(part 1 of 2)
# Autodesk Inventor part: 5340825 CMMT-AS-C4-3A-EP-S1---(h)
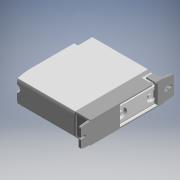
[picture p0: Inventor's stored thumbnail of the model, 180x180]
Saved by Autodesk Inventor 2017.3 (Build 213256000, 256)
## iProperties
Part Number: 5340825 CMMT-AS-C4-3A-EP-S1---(h)
Material: Generic
Catalog Web Link: www.cadenas.de
Description: CMMT-h-housing
Vendor: FESTO
Document SubType Name: Modeling
Designer: partserver
Manufacturer: FESTO
Mass: 1385.12 g
Surface Area: 1266.44 cm^2
Volume: 1385.12 cm^3
Density: 1 g/cm^3
Appearance: PSOLRGB-255-255-255
Category: PARTsolutions
Company: FESTO
Title: 5340825 CMMT-AS-C4-3A-EP-S1---(h)
Author: Cadenas PARTsolutions
Comments: housing
PSOL_IDENT_0: {$CADENAS_DATA\23d-libs\festo\parts\c\cmmt\parts\cmmt_housing.prj},207 {VTYP=3D},{NB=5340825 CMMT-AS
PSOL_IDENT_1: -C4-3A-EP-S1---(h)},{LINA=5340825 CMMT-AS-C4-3A-EP-S1---(h)},{NN=CMMT-h},{DATE=07.10.2020 12:11:43},
PSOL_IDENT_2: {GEOMDATE=07.10.2020 12:11:39},{VERSION=},{LINEID=130},{WBVAR=},{WBNUMERIC=}  {NB=5340825 CMMT-AS-C4
PSOL_IDENT_3: -3A-EP-S1---(h)},{LINA=5340825 CMMT-AS-C4-3A-EP-S1---(h)},{KT=DUMMY},{TNR=5340825},{TYP=CMMT-AS-C4-3
PSOL_IDENT_4: A-EP-S1},{NEN=C4},{NES=3A},{BUS=EP},{B1=0.000},{B2=0.000},{B3=0.000},{D1=0.000},{D2=0.000},{D3=0.000
PSOL_IDENT_5: },{H1=0.000},{H2=0.000},{L1=0.000},{L2=0.000},{L3=0.000},{L4=0.000},{L5=0.000},{L6=0.000},{L7=0.000}
PSOL_IDENT_6: ,{B4=0.000},{B5=MIN},{B6=MIN},{L8=MIN}
NB: 5340825 CMMT-AS-C4-3A-EP-S1---(h)
NN: CMMT-h
NT: housing
NBSYN: $TNR. $TYP.---(h)
LINA: 5340825 CMMT-AS-C4-3A-EP-S1---(h)
CATALOG: Festo
TNR: 5340825
TYP: CMMT-AS-C4-3A-EP-S1
NEN: C4
NES: 3A
BUS: EP
B1: 0
B2: 0
B3: 0
D1: 0
D2: 0
D3: 0
H1: 0
H2: 0
L1: 0
L2: 0
L3: 0
L4: 0
L5: 0
L6: 0
L7: 0
B4: 0
B5: 0
B6: 0
L8: 0
SUPPLIER: FESTO
ARTICLENO: 5340825 CMMT-AS-C4-3A-EP-S1---(h)
BOMINFO: 5340825 CMMT-AS-C4-3A-EP-S1---(h)
CREATOR: CADENAS GmbH
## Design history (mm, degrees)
sketch "Sketch_1"
  geometry: L1 (82.734, 24.995)-(-82.734, 24.995); L2 (-84.995, 14.49)-(-84.995, -15.51); L3 (-82.734, -24.995)-(82.734, -24.995); L4 (84.995, -15.51)-(84.995, 14.49); A1 r 0.4 centre (-82.734, 24.595) between (-82.734, 24.995) and (-83.105, 24.745); A2 r 26.005 centre (-58.995, 15) between (-83.105, 24.745) and (-84.995, 14.49); A3 r 26.005 centre (-58.995, -15) between (-84.995, -15.51) and (-83.105, -24.745); A4 r 0.4 centre (-82.734, -24.595) between (-83.105, -24.745) and (-82.734, -24.995); A5 r 0.4 centre (82.734, -24.595) between (82.734, -24.995) and (83.105, -24.745); A6 r 26.005 centre (58.995, -15) between (83.105, -24.745) and (84.995, -15.51); A7 r 26.005 centre (58.995, 15) between (84.995, 14.49) and (83.105, 24.745); A8 r 0.4 centre (82.734, 24.595) between (83.105, 24.745) and (82.734, 24.995)
  constraints: 16 point on circle, 8 centre point, 8 end point
extrude "Extrusion1" join sketch "Sketch_1" distance "d0" = 35; taper "d1" = 0 deg
sketch "Sketch_2"
  geometry: L1 (-105, 18.471)-(-105, 3.55); L2 (-104.2, 2.75)-(-97, 2.75); L3 (-97, -2.75)-(-104.2, -2.75); L4 (-105, -3.55)-(-105, -18.471); L5 (-75, -23.598)-(77, -23.598); L6 (107, -18.471)-(107, 18.471); L7 (77, 23.598)-(-75, 23.598); A1 r 165 centre (-75.823, -141.4) between (-75, 23.598) and (-102.485, 21.432); A2 r 3 centre (-102, 18.471) between (-102.485, 21.432) and (-105, 18.471); A3 r 0.8 centre (-104.2, 3.55) between (-105, 3.55) and (-104.2, 2.75); A4 r 2.75 centre (-97, 0) between (-97, -2.75) and (-97, 2.75); A5 r 0.8 centre (-104.2, -3.55) between (-104.2, -2.75) and (-105, -3.55); A6 r 3 centre (-102, -18.471) between (-105, -18.471) and (-102.485, -21.432); A7 r 165 centre (-75.823, 141.4) between (-102.485, -21.432) and (-75, -23.598); A8 r 165 centre (77.823, 141.4) between (77, -23.598) and (104.485, -21.432); A9 r 3 centre (104, -18.471) between (104.485, -21.432) and (107, -18.471); A10 r 3 centre (104, 18.471) between (107, 18.471) and (104.485, 21.432); A11 r 165 centre (77.823, -141.4) between (104.485, 21.432) and (77, 23.598)
  constraints: 22 point on circle, 14 end point, 11 centre point
extrude "Extrusion2" join sketch "Sketch_2" distance "d2" = 5; taper "d3" = 0 deg
sketch "Sketch_3"
  geometry: L1 (96.309, -2.75)-(101, -2.75); L2 (101, 2.75)-(96.309, 2.75); A1 r 5.5 centre (91, 0) between (95.492, 3.173) and (95.492, -3.173); A2 r 1 centre (96.309, -3.75) between (96.309, -2.75) and (95.492, -3.173); A3 r 2.75 centre (101, 0) between (101, -2.75) and (101, 2.75); A4 r 1 centre (96.309, 3.75) between (95.492, 3.173) and (96.309, 2.75)
  constraints: 8 point on circle, 4 centre point, 4 end point
extrude "Extrusion3" cut sketch "Sketch_3" distance "d4" = 5; taper "d5" = 0 deg
sketch "Sketch_4"
  geometry: L1 (5, -21.75)-(30.75, -21.75); L2 (31.75, -20.75)-(31.75, 20.75); L3 (30.75, 21.75)-(5, 21.75); L4 (5, 21.75)-(5, -21.75); A1 r 1 centre (30.75, -20.75) between (30.75, -21.75) and (31.75, -20.75); A2 r 1 centre (30.75, 20.75) between (31.75, 20.75) and (30.75, 21.75)
  constraints: 8 end point, 4 point on circle, 2 centre point
extrude "Extrusion4" cut sketch "Sketch_4" distance "d6" = 2; taper "d7" = 0 deg
sketch "Sketch_5"
  geometry: L1 (5, -21.75)-(30.75, -21.75); L2 (31.75, -20.75)-(31.75, 20.75); L3 (30.75, 21.75)-(5, 21.75); L4 (5, 21.75)-(5, -21.75); A1 r 1 centre (30.75, -20.75) between (30.75, -21.75) and (31.75, -20.75); A2 r 1 centre (30.75, 20.75) between (31.75, 20.75) and (30.75, 21.75)
  constraints: 8 end point, 4 point on circle, 2 centre point
extrude "Extrusion5" cut sketch "Sketch_5" distance "d8" = 2; taper "d9" = 0 deg
sketch "Sketch_6"
  geometry: L1 (-28.75, 88)-(-28.75, -85); L2 (-28.75, -85)-(-23.75, -85); L3 (-23.75, -85)-(-23.75, 81.348); L4 (-15, 83)-(15, 83); L5 (23.75, 81.348)-(23.75, -85); L6 (23.75, -85)-(28.75, -85); L7 (28.75, -85)-(28.75, 88); L8 (28.75, 88)-(-28.75, 88); A1 r 24 centre (-15, 59) between (-15, 83) and (-23.75, 81.348); A2 r 24 centre (15, 59) between (23.75, 81.348) and (15, 83)
  constraints: 16 end point, 4 point on circle, 2 centre point
extrude "Extrusion6" cut sketch "Sketch_6" distance "d10" = 0.5; taper "d11" = 0 deg
sketch "Sketch_52"
  geometry: L1 (-25, 82.732)-(-25, -82.734); L2 (-15, -85.002)-(15, -85.002); L3 (25, -82.734)-(25, 82.732); L4 (15, 85)-(-15, 85); A1 r 0.4 centre (-24.6, -82.734) between (-25, -82.734) and (-24.75, -83.105); A2 r 26 centre (-15, -59.002) between (-24.75, -83.105) and (-15, -85.002); A3 r 26 centre (15, -59.002) between (15, -85.002) and (24.75, -83.105); A4 r 0.4 centre (24.6, -82.734) between (24.75, -83.105) and (25, -82.734); A5 r 0.4 centre (24.6, 82.732) between (25, 82.732) and (24.75, 83.103); A6 r 26 centre (15, 59) between (24.75, 83.103) and (15, 85); A7 r 26 centre (-15, 59) between (-15, 85) and (-24.75, 83.103); A8 r 0.4 centre (-24.6, 82.732) between (-24.75, 83.103) and (-25, 82.732)
  constraints: 16 point on circle, 8 centre point, 8 end point
extrude "Extrusion7" join sketch "Sketch_52" distance "d12" = 135.3; taper "d13" = 0 deg
sketch "Sketch_7"
  geometry: L1 (162.15, 50)-(169.9, 50); L2 (170.3, 49.6)-(170.3, -45); L3 (165.299, -85.003)-(176.75, -85.003); L4 (176.75, -85.003)-(176.75, 85); L5 (176.75, 85)-(161.75, 85); L6 (161.75, 85)-(161.75, 50.4); A1 r 0.4 centre (162.15, 50.4) between (161.75, 50.4) and (162.15, 50); A2 r 0.4 centre (169.9, 49.6) between (170.3, 49.6) and (169.9, 50); A3 r 162.5 centre (7.8, -45) between (165.299, -85.003) and (170.3, -45)
  constraints: 12 end point, 6 point on circle, 3 centre point
extrude "Extrusion8" cut sketch "Sketch_7" stored distance "d14" = 50; taper "d15" = 0 deg
sketch "Sketch_53"
  geometry: L1 (55.07, 6.487)-(73.185, 6.487); L2 (73.435, 6.737)-(73.435, 16.656); L3 (73.185, 16.906)-(55.07, 16.906); L4 (54.82, 16.656)-(54.82, 6.737); A1 r 0.25 centre (55.07, 6.737) between (54.82, 6.737) and (55.07, 6.487); A2 r 0.25 centre (73.185, 6.737) between (73.185, 6.487) and (73.435, 6.737); A3 r 0.25 centre (73.185, 16.656) between (73.435, 16.656) and (73.185, 16.906); A4 r 0.25 centre (55.07, 16.656) between (55.07, 16.906) and (54.82, 16.656)
  constraints: 8 end point, 8 point on circle, 4 centre point
extrude "Extrusion9" cut sketch "Sketch_53" distance "d16" = 8.5; taper "d17" = 0 deg
sketch "Sketch_54"
  geometry: L1 (58.43, 14.115)-(58.43, 9.2); L2 (58.43, 9.2)-(59.93, 9.2); L3 (59.93, 9.2)-(59.537, 9.88); L4 (59.537, 9.88)-(62.838, 9.88); L5 (62.838, 9.88)-(62.445, 9.2); L6 (62.445, 9.2)-(64.065, 9.2); L7 (64.065, 9.2)-(64.065, 14.115); L8 (64.065, 14.115)-(63.311, 14.115); L9 (59.069, 14.115)-(58.43, 14.115); A1 r 2.915 centre (61.19, 12.115) between (63.311, 14.115) and (59.069, 14.115)
  constraints: 18 end point, 2 point on circle, 1 centre point
extrude "Extrusion10" join sketch "Sketch_54" distance "d18" = 8.45; taper "d19" = 0 deg
sketch "Sketch_55"
  geometry: L1 (65.922, 14.115)-(65.922, 9.2); L2 (65.922, 9.2)-(67.422, 9.2); L3 (67.422, 9.2)-(67.029, 9.88); L4 (67.029, 9.88)-(70.33, 9.88); L5 (70.33, 9.88)-(69.937, 9.2); L6 (69.937, 9.2)-(71.557, 9.2); L7 (71.557, 9.2)-(71.557, 14.115); L8 (71.557, 14.115)-(70.931, 14.115); L9 (66.689, 14.115)-(65.922, 14.115); A1 r 2.915 centre (68.81, 12.115) between (70.931, 14.115) and (66.689, 14.115)
  constraints: 18 end point, 2 point on circle, 1 centre point
extrude "Extrusion11" join sketch "Sketch_55" distance "d20" = 8.45; taper "d21" = 0 deg
sketch "Sketch_11"
  geometry: L1 (77.977, 7.387)-(118.562, 7.387); L2 (118.812, 7.637)-(118.812, 17.55); L3 (118.562, 17.8)-(113.786, 17.8); L4 (113.536, 18.05)-(113.536, 18.85); L5 (113.286, 19.1)-(111.913, 19.1); L6 (111.663, 18.85)-(111.663, 18.05); L7 (111.413, 17.8)-(86.786, 17.8); L8 (86.536, 18.05)-(86.536, 18.85); L9 (86.286, 19.1)-(84.913, 19.1); L10 (84.663, 18.85)-(84.663, 18.05); L11 (84.413, 17.8)-(77.977, 17.8); L12 (77.727, 17.55)-(77.727, 7.637); A1 r 0.25 centre (77.977, 7.637) between (77.727, 7.637) and (77.977, 7.387); A2 r 0.25 centre (118.562, 7.637) between (118.562, 7.387) and (118.812, 7.637); A3 r 0.25 centre (118.562, 17.55) between (118.812, 17.55) and (118.562, 17.8); A4 r 0.25 centre (113.786, 18.05) between (113.536, 18.05) and (113.786, 17.8); A5 r 0.25 centre (113.286, 18.85) between (113.536, 18.85) and (113.286, 19.1); A6 r 0.25 centre (111.913, 18.85) between (111.913, 19.1) and (111.663, 18.85); A7 r 0.25 centre (111.413, 18.05) between (111.413, 17.8) and (111.663, 18.05); A8 r 0.25 centre (86.786, 18.05) between (86.536, 18.05) and (86.786, 17.8); A9 r 0.25 centre (86.286, 18.85) between (86.536, 18.85) and (86.286, 19.1); A10 r 0.25 centre (84.913, 18.85) between (84.913, 19.1) and (84.663, 18.85); A11 r 0.25 centre (84.413, 18.05) between (84.413, 17.8) and (84.663, 18.05); A12 r 0.25 centre (77.977, 17.55) between (77.977, 17.8) and (77.727, 17.55)
  constraints: 24 end point, 24 point on circle, 12 centre point
extrude "Extrusion12" cut sketch "Sketch_11" distance "d22" = 8.5; taper "d23" = 0 deg
sketch "Sketch_10"
  geometry: L1 (80.34, 16.9)-(80.34, 8.33); L2 (80.34, 8.33)-(117.9, 8.33); L3 (117.9, 8.33)-(117.9, 16.9); L4 (117.9, 16.9)-(80.34, 16.9)
  constraints: 8 end point
extrude "Extrusion13" join sketch "Sketch_10" distance "d24" = 8.45; taper "d25" = 0 deg
sketch "Sketch_12"
  geometry: L1 (81.14, 10)-(81.809, 10); L2 (85.951, 10)-(86.889, 10); L3 (91.031, 10)-(91.969, 10); L4 (96.111, 10)-(97.049, 10); L5 (101.191, 10)-(102.129, 10); L6 (106.271, 10)-(107.209, 10); L7 (111.351, 10)-(112.289, 10); L8 (116.431, 10)-(117.1, 10); L9 (117.1, 10)-(117.1, 15.3); L10 (117.1, 15.3)-(81.14, 15.3); L11 (81.14, 15.3)-(81.14, 10); A1 r 3.08 centre (83.88, 12.28) between (81.809, 10) and (85.951, 10); A2 r 3.08 centre (88.96, 12.28) between (86.889, 10) and (91.031, 10); A3 r 3.08 centre (94.04, 12.28) between (91.969, 10) and (96.111, 10); A4 r 3.08 centre (99.12, 12.28) between (97.049, 10) and (101.191, 10); A5 r 3.08 centre (104.2, 12.28) between (102.129, 10) and (106.271, 10); A6 r 3.08 centre (109.28, 12.28) between (107.209, 10) and (111.351, 10); A7 r 3.08 centre (114.36, 12.28) between (112.289, 10) and (116.431, 10)
  constraints: 22 end point, 14 point on circle, 7 centre point
extrude "Extrusion14" cut sketch "Sketch_12" distance "d26" = 8.5; taper "d27" = 0 deg
sketch "Sketch_13"
  geometry: L1 (61.19, 78)-(61.19, 85); L2 (61.19, 85)-(62.59, 85); L3 (62.59, 85)-(62.59, 84); L4 (62.59, 84)-(61.94, 84); L5 (61.94, 84)-(61.94, 78); L6 (61.94, 78)-(61.19, 78); L7 (61.19, 78)-(61.19, 85)
  constraints: 14 end point
revolve "Revolution1" sketch "Sketch_13" stored, may be unused: angle "d28" = 360 deg
pattern_linear "Rectangular Pattern1" dims "d31" = 7.62, "d34" = 0
sketch "Sketch_16"
  geometry: L1 (83.38, 12.48)-(83.38, 11.92); L2 (83.6, 11.7)-(84.16, 11.7); L3 (84.38, 11.92)-(84.38, 12.48); L4 (84.16, 12.7)-(83.6, 12.7); A1 r 0.22 centre (83.6, 11.92) between (83.38, 11.92) and (83.6, 11.7); A2 r 0.22 centre (84.16, 11.92) between (84.16, 11.7) and (84.38, 11.92); A3 r 0.22 centre (84.16, 12.48) between (84.38, 12.48) and (84.16, 12.7); A4 r 0.22 centre (83.6, 12.48) between (83.6, 12.7) and (83.38, 12.48)
  constraints: 8 end point, 8 point on circle, 4 centre point
extrude "Extrusion15" join sketch "Sketch_16" distance "d35" = 7.3; taper "d36" = 0 deg
pattern_linear "Rectangular Pattern2" dims "d39" = 5.08, "d42" = 0
sketch "Sketch_18"
  geometry: L1 (83.88, 76.5)-(83.88, 77.5); L2 (83.88, 77.5)-(85.18, 77.5); L3 (85.18, 77.5)-(85.28, 76.5); L4 (85.28, 76.5)-(83.88, 76.5); L5 (83.88, 76.5)-(83.88, 77.5)
  constraints: 10 end point
revolve "Revolution2" sketch "Sketch_18" stored, may be unused: angle "d43" = 360 deg
pattern_linear "Rectangular Pattern3" dims "d46" = 5.08, "d49" = 0
sketch "Sketch_15"
  geometry: L1 (71.887, -0.537)-(71.887, -17.053); L2 (72.137, -17.303)-(156.162, -17.303); L3 (156.412, -17.053)-(156.412, -0.537); L4 (156.162, -0.287)-(72.137, -0.287); A1 r 0.25 centre (72.137, -17.054) between (71.887, -17.053) and (72.137, -17.303); A2 r 0.25 centre (156.162, -17.054) between (156.162, -17.303) and (156.412, -17.053); A3 r 0.25 centre (156.162, -0.537) between (156.412, -0.537) and (156.162, -0.287); A4 r 0.25 centre (72.137, -0.537) between (72.137, -0.287) and (71.887, -0.537)
  constraints: 8 end point, 8 point on circle, 4 centre point
extrude "Extrusion16" cut sketch "Sketch_15" distance "d50" = 8.5; taper "d51" = 0 deg
sketch "Sketch_20"
  geometry: L1 (74.5, -16.4)-(117.9, -16.4); L2 (117.9, -16.4)-(117.9, -1.2); L3 (117.9, -1.2)-(74.5, -1.2); L4 (74.5, -1.2)-(74.5, -16.4)
  constraints: 8 end point
extrude "Extrusion17" join sketch "Sketch_20" distance "d52" = 8.45; taper "d53" = 0 deg
sketch "Sketch_56"
  geometry: L1 (121.09, -16.375)-(153.348, -16.375); L2 (153.348, -16.375)-(153.348, -3.04); L3 (153.348, -3.04)-(121.09, -3.04); L4 (121.09, -3.04)-(121.09, -16.375)
  constraints: 8 end point
extrude "Extrusion18" join sketch "Sketch_56" distance "d54" = 8.45; taper "d55" = 0 deg
sketch "Sketch_21"
  geometry: L1 (75.4, -3.2)-(75.4, -7.5); L2 (75.4, -7.5)-(76.05, -7.5); L3 (77.85, -7.5)-(78.5, -7.5); L4 (78.5, -7.5)-(78.5, -3.2); L5 (78.5, -3.2)-(77.35, -3.2); L6 (77.35, -3.2)-(77.35, -2.73); L7 (77.55, -2.53)-(78.047, -2.53); L8 (78.047, -2.53)-(78.44, -1.85); L9 (78.44, -1.85)-(75.46, -1.85); L10 (75.46, -1.85)-(75.853, -2.53); L11 (75.853, -2.53)-(76.35, -2.53); L12 (76.55, -2.73)-(76.55, -3.2); L13 (76.55, -3.2)-(75.4, -3.2); A1 r 1.5 centre (76.95, -8.7) between (77.85, -7.5) and (76.05, -7.5); A2 r 0.2 centre (77.55, -2.73) between (77.55, -2.53) and (77.35, -2.73); A3 r 0.2 centre (76.35, -2.73) between (76.55, -2.73) and (76.35, -2.53)
  constraints: 26 end point, 6 point on circle, 3 centre point
extrude "Extrusion19" cut sketch "Sketch_21" distance "d56" = 6.6; taper "d57" = 0 deg
sketch "Sketch_23"
  geometry: L1 (75.4, -9.45)-(78.4, -9.45); L2 (78.4, -9.45)-(78.4, -8.15); L3 (78.4, -8.15)-(75.4, -8.15); L4 (75.4, -8.15)-(75.4, -9.45)
  constraints: 8 end point
extrude "Extrusion20" cut sketch "Sketch_23" distance "d64" = 11.1; taper "d65" = 0 deg
sketch "Pattern_5_SKETCH_1"
  geometry: L1 (79, -9.45)-(82, -9.45); L2 (82, -9.45)-(82, -8.15); L3 (82, -8.15)-(79, -8.15); L4 (79, -8.15)-(79, -9.45)
  constraints: 8 end point
sketch "Pattern_5_SKETCH_2"
  geometry: L1 (82.5, -9.45)-(85.5, -9.45); L2 (85.5, -9.45)-(85.5, -8.15); L3 (85.5, -8.15)-(82.5, -8.15); L4 (82.5, -8.15)-(82.5, -9.45)
  constraints: 8 end point
sketch "Pattern_5_SKETCH_3"
  geometry: L1 (86, -9.45)-(89, -9.45); L2 (89, -9.45)-(89, -8.15); L3 (89, -8.15)-(86, -8.15); L4 (86, -8.15)-(86, -9.45)
  constraints: 8 end point
sketch "Pattern_5_SKETCH_4"
  geometry: L1 (89.5, -9.45)-(92.5, -9.45); L2 (92.5, -9.45)-(92.5, -8.15); L3 (92.5, -8.15)-(89.5, -8.15); L4 (89.5, -8.15)-(89.5, -9.45)
  constraints: 8 end point
sketch "Pattern_5_SKETCH_5"
  geometry: L1 (93, -9.45)-(96, -9.45); L2 (96, -9.45)-(96, -8.15); L3 (96, -8.15)-(93, -8.15); L4 (93, -8.15)-(93, -9.45)
  constraints: 8 end point
sketch "Pattern_5_SKETCH_6"
  geometry: L1 (96.5, -9.45)-(99.5, -9.45); L2 (99.5, -9.45)-(99.5, -8.15); L3 (99.5, -8.15)-(96.5, -8.15); L4 (96.5, -8.15)-(96.5, -9.45)
  constraints: 8 end point
sketch "Pattern_5_SKETCH_7"
  geometry: L1 (100, -9.45)-(103, -9.45); L2 (103, -9.45)-(103, -8.15); L3 (103, -8.15)-(100, -8.15); L4 (100, -8.15)-(100, -9.45)
  constraints: 8 end point
sketch "Pattern_5_SKETCH_8"
  geometry: L1 (103.5, -9.45)-(106.5, -9.45); L2 (106.5, -9.45)-(106.5, -8.15); L3 (106.5, -8.15)-(103.5, -8.15); L4 (103.5, -8.15)-(103.5, -9.45)
  constraints: 8 end point
sketch "Pattern_5_SKETCH_9"
  geometry: L1 (107, -9.45)-(110, -9.45); L2 (110, -9.45)-(110, -8.15); L3 (110, -8.15)-(107, -8.15); L4 (107, -8.15)-(107, -9.45)
  constraints: 8 end point
sketch "Pattern_5_SKETCH_10"
  geometry: L1 (110.5, -9.45)-(113.5, -9.45); L2 (113.5, -9.45)-(113.5, -8.15); L3 (113.5, -8.15)-(110.5, -8.15); L4 (110.5, -8.15)-(110.5, -9.45)
  constraints: 8 end point
sketch "Pattern_5_SKETCH_11"
  geometry: L1 (114, -9.45)-(117, -9.45); L2 (117, -9.45)-(117, -8.15); L3 (117, -8.15)-(114, -8.15); L4 (114, -8.15)-(114, -9.45)
  constraints: 8 end point
extrude "Extrusion21" cut sketch "Pattern_5_SKETCH_1" distance "d66" = 11.1; taper "d67" = 0 deg
extrude "Extrusion22" cut sketch "Pattern_5_SKETCH_2" distance "d68" = 11.1; taper "d69" = 0 deg
extrude "Extrusion23" cut sketch "Pattern_5_SKETCH_3" distance "d70" = 11.1; taper "d71" = 0 deg
extrude "Extrusion24" cut sketch "Pattern_5_SKETCH_4" distance "d72" = 11.1; taper "d73" = 0 deg
extrude "Extrusion25" cut sketch "Pattern_5_SKETCH_5" distance "d74" = 11.1; taper "d75" = 0 deg
extrude "Extrusion26" cut sketch "Pattern_5_SKETCH_6" distance "d76" = 11.1; taper "d77" = 0 deg
extrude "Extrusion27" cut sketch "Pattern_5_SKETCH_7" distance "d78" = 11.1; taper "d79" = 0 deg
extrude "Extrusion28" cut sketch "Pattern_5_SKETCH_8" distance "d80" = 11.1; taper "d81" = 0 deg
extrude "Extrusion29" cut sketch "Pattern_5_SKETCH_9" distance "d82" = 11.1; taper "d83" = 0 deg
extrude "Extrusion30" cut sketch "Pattern_5_SKETCH_10" distance "d84" = 11.1; taper "d85" = 0 deg
extrude "Extrusion31" cut sketch "Pattern_5_SKETCH_11" distance "d86" = 11.1; taper "d87" = 0 deg
sketch "Sketch_25"
  geometry: L1 (76.55, -5.6)-(77.35, -5.6); L2 (77.35, -5.6)-(77.35, -4.8); L3 (77.35, -4.8)-(76.55, -4.8); L4 (76.55, -4.8)-(76.55, -5.6)
  constraints: 8 end point
extrude "Extrusion32" join sketch "Sketch_25" distance "d88" = 5.4; taper "d89" = 0 deg
sketch "Sketch_27"
  geometry: L1 (123.39, -6.648)-(123.39, -13.6); L2 (123.39, -13.6)-(135.303, -13.6); L3 (135.303, -13.6)-(135.303, -6.648); L4 (135.303, -6.648)-(132.496, -6.648); L5 (132.496, -6.648)-(132.496, -5.04); L6 (132.496, -5.04)-(131.378, -5.04); L7 (131.378, -5.04)-(131.378, -3.897); L8 (131.378, -3.897)-(127.315, -3.897); L9 (127.315, -3.897)-(127.315, -5.04); L10 (127.315, -5.04)-(126.197, -5.04); L11 (126.197, -5.04)-(126.197, -6.648); L12 (126.197, -6.648)-(123.39, -6.648)
  constraints: 24 end point
extrude "Extrusion33" cut sketch "Sketch_27" distance "d96" = 10.1; taper "d97" = 0 deg
pattern_linear "Rectangular Pattern6" dims "d100" = 15.746, "d103" = 0
sketch "Sketch_29"
  geometry: L1 (-17.47, 67.27)-(-17.47, 53.33); L2 (-16.97, 52.83)-(-11.53, 52.83); L3 (-11.03, 53.33)-(-11.03, 67.27); L4 (-11.53, 67.77)-(-16.97, 67.77); A1 r 0.5 centre (-16.97, 53.33) between (-17.47, 53.33) and (-16.97, 52.83); A2 r 0.5 centre (-11.53, 53.33) between (-11.53, 52.83) and (-11.03, 53.33); A3 r 0.5 centre (-11.53, 67.27) between (-11.03, 67.27) and (-11.53, 67.77); A4 r 0.5 centre (-16.97, 67.27) between (-16.97, 67.77) and (-17.47, 67.27)
  constraints: 8 end point, 8 point on circle, 4 centre point
extrude "Extrusion34" cut sketch "Sketch_29" distance "d104" = 6; taper "d105" = 0 deg
sketch "Sketch_30"
  geometry: L1 (-16.35, 55.176)-(-12.15, 55.176); L2 (-12.15, 55.176)-(-12.15, 65.546); L3 (-12.15, 65.546)-(-16.35, 65.546); L4 (-16.35, 65.546)-(-16.35, 55.176); L5 (-15.875, 64.646)-(-15.875, 56.076); L6 (-15.875, 56.076)-(-14.4, 56.076); L7 (-14.4, 56.076)-(-14.4, 55.576); L8 (-14.4, 55.576)-(-12.625, 55.576); L9 (-12.625, 55.576)-(-12.625, 65.146); L10 (-12.625, 65.146)-(-14.4, 65.146); L11 (-14.4, 65.146)-(-14.4, 64.646); L12 (-14.4, 64.646)-(-15.875, 64.646)
  constraints: 24 end point
extrude "Extrusion35" join sketch "Sketch_30" distance "d106" = 5; taper "d107" = 0 deg
sketch "Sketch_31"
  geometry: L1 (-15.035, 63.326)-(-14.735, 63.326); L2 (-14.735, 63.326)-(-14.735, 63.746); L3 (-14.735, 63.746)-(-15.035, 63.746); L4 (-15.035, 63.746)-(-15.035, 63.326)
  constraints: 8 end point
extrude "Extrusion36" join sketch "Sketch_31" stored distance "d108" = 8; taper "d109" = 0 deg
pattern_linear "Rectangular Pattern7" dims "d112" = 1.27, "d115" = 1.27
sketch "Sketch_35"
  geometry: L1 (-17.463, 36.213)-(-17.463, 4.087); L2 (-16.463, 3.087)-(-3.001, 3.087); L3 (-2.001, 4.087)-(-2.001, 36.213); L4 (-3.001, 37.213)-(-16.463, 37.213); A1 r 1 centre (-16.463, 4.087) between (-17.463, 4.087) and (-16.463, 3.087); A2 r 1 centre (-3.001, 4.087) between (-3.001, 3.087) and (-2.001, 4.087); A3 r 1 centre (-3.001, 36.213) between (-2.001, 36.213) and (-3.001, 37.213); A4 r 1 centre (-16.463, 36.213) between (-16.463, 37.213) and (-17.463, 36.213)
  constraints: 8 end point, 8 point on circle, 4 centre point
extrude "Extrusion37" cut sketch "Sketch_35" distance "d116" = 11.7; taper "d117" = 0 deg
sketch "Sketch_36"
  geometry: L1 (-17.463, 0.713)-(-17.463, -31.413); L2 (-16.463, -32.413)-(-3.001, -32.413); L3 (-2.001, -31.413)-(-2.001, 0.713); L4 (-3.001, 1.713)-(-16.463, 1.713); A1 r 1 centre (-16.463, -31.413) between (-17.463, -31.413) and (-16.463, -32.413); A2 r 1 centre (-3.001, -31.413) between (-3.001, -32.413) and (-2.001, -31.413); A3 r 1 centre (-3.001, 0.713) between (-2.001, 0.713) and (-3.001, 1.713); A4 r 1 centre (-16.463, 0.713) between (-16.463, 1.713) and (-17.463, 0.713)
  constraints: 8 end point, 8 point on circle, 4 centre point
extrude "Extrusion38" cut sketch "Sketch_36" distance "d118" = 11.7; taper "d119" = 0 deg
sketch "Sketch_33"
  geometry: L1 (-16.375, 3.871)-(-3.04, 3.871); L2 (-3.04, 3.871)-(-3.04, 36.129); L3 (-3.04, 36.129)-(-16.375, 36.129); L4 (-16.375, 36.129)-(-16.375, 3.871); L5 (-13.6, 21.917)-(-6.648, 21.917); L6 (-6.648, 21.917)-(-6.648, 24.724); L7 (-6.648, 24.724)-(-5.04, 24.724); L8 (-5.04, 24.724)-(-5.04, 25.842); L9 (-5.04, 25.842)-(-3.897, 25.842); L10 (-3.897, 25.842)-(-3.897, 29.905); L11 (-3.897, 29.905)-(-5.04, 29.905); L12 (-5.04, 29.905)-(-5.04, 31.023); L13 (-5.04, 31.023)-(-6.648, 31.023); L14 (-6.648, 31.023)-(-6.648, 33.83); L15 (-6.648, 33.83)-(-13.6, 33.83); L16 (-13.6, 33.83)-(-13.6, 21.917); L17 (-13.6, 6.169)-(-6.648, 6.169); L18 (-6.648, 6.169)-(-6.648, 8.976); L19 (-6.648, 8.976)-(-5.04, 8.976); L20 (-5.04, 8.976)-(-5.04, 10.094); L21 (-5.04, 10.094)-(-3.897, 10.094); L22 (-3.897, 10.094)-(-3.897, 14.157); L23 (-3.897, 14.157)-(-5.04, 14.157); L24 (-5.04, 14.157)-(-5.04, 15.275); L25 (-5.04, 15.275)-(-6.648, 15.275); L26 (-6.648, 15.275)-(-6.648, 18.082); L27 (-6.648, 18.082)-(-13.6, 18.082); L28 (-13.6, 18.082)-(-13.6, 6.169)
  constraints: 56 end point
extrude "Extrusion39" join sketch "Sketch_33" distance "d120" = 10.1; taper "d121" = 0 deg
sketch "Sketch_34"
  geometry: L1 (-16.375, -31.329)-(-3.04, -31.329); L2 (-3.04, -31.329)-(-3.04, 0.929); L3 (-3.04, 0.929)-(-16.375, 0.929); L4 (-16.375, 0.929)-(-16.375, -31.329); L5 (-13.6, -13.283)-(-6.648, -13.283); L6 (-6.648, -13.283)-(-6.648, -10.476); L7 (-6.648, -10.476)-(-5.04, -10.476); L8 (-5.04, -10.476)-(-5.04, -9.358); L9 (-5.04, -9.358)-(-3.897, -9.358); L10 (-3.897, -9.358)-(-3.897, -5.295); L11 (-3.897, -5.295)-(-5.04, -5.295); L12 (-5.04, -5.295)-(-5.04, -4.177); L13 (-5.04, -4.177)-(-6.648, -4.177); L14 (-6.648, -4.177)-(-6.648, -1.37); L15 (-6.648, -1.37)-(-13.6, -1.37); L16 (-13.6, -1.37)-(-13.6, -13.283); L17 (-13.6, -29.031)-(-6.648, -29.031); L18 (-6.648, -29.031)-(-6.648, -26.224); L19 (-6.648, -26.224)-(-5.04, -26.224); L20 (-5.04, -26.224)-(-5.04, -25.106); L21 (-5.04, -25.106)-(-3.897, -25.106); L22 (-3.897, -25.106)-(-3.897, -21.043); L23 (-3.897, -21.043)-(-5.04, -21.043); L24 (-5.04, -21.043)-(-5.04, -19.925); L25 (-5.04, -19.925)-(-6.648, -19.925); L26 (-6.648, -19.925)-(-6.648, -17.118); L27 (-6.648, -17.118)-(-13.6, -17.118); L28 (-13.6, -17.118)-(-13.6, -29.031)
  constraints: 56 end point
extrude "Extrusion40" join sketch "Sketch_34" distance "d122" = 10.1; taper "d123" = 0 deg
sketch "Sketch_37"
  geometry: L1 (5.137, 16.787)-(16.063, 16.787); L2 (17.063, 17.787)-(17.063, 36.213); L3 (16.063, 37.213)-(5.137, 37.213); L4 (4.137, 36.213)-(4.137, 17.787); A1 r 1 centre (5.137, 17.787) between (4.137, 17.787) and (5.137, 16.787); A2 r 1 centre (16.063, 17.787) between (16.063, 16.787) and (17.063, 17.787); A3 r 1 centre (16.063, 36.213) between (17.063, 36.213) and (16.063, 37.213); A4 r 1 centre (5.137, 36.213) between (5.137, 37.213) and (4.137, 36.213)
  constraints: 8 end point, 8 point on circle, 4 centre point
extrude "Extrusion41" cut sketch "Sketch_37" distance "d124" = 8.5; taper "d125" = 0 deg
sketch "Sketch_38"
  geometry: L1 (5.137, 0.287)-(6.437, 0.287); L2 (6.937, -0.213)-(6.937, -22.263); L3 (7.937, -23.263)-(16.063, -23.263); L4 (17.063, -22.263)-(17.063, 12.703); L5 (16.053, 13.713)-(5.137, 13.713); L6 (4.137, 12.713)-(4.137, 1.287); A1 r 1 centre (5.137, 1.287) between (4.137, 1.287) and (5.137, 0.287); A2 r 0.5 centre (6.437, -0.213) between (6.937, -0.213) and (6.437, 0.287); A3 r 1 centre (7.937, -22.263) between (6.937, -22.263) and (7.937, -23.263); A4 r 1 centre (16.063, -22.263) between (16.063, -23.263) and (17.063, -22.263); A5 r 1.01 centre (16.053, 12.703) between (17.063, 12.703) and (16.053, 13.713); A6 r 1 centre (5.137, 12.713) between (5.137, 13.713) and (4.137, 12.713)
  constraints: 12 end point, 12 point on circle, 6 centre point
extrude "Extrusion42" cut sketch "Sketch_38" distance "d126" = 8.5; taper "d127" = 0 deg
sketch "Sketch_39"
  geometry: L1 (5.2, 17.85)-(16, 17.85); L2 (16, 17.85)-(16, 36.15); L3 (16, 36.15)-(5.2, 36.15); L4 (5.2, 36.15)-(5.2, 17.85); L5 (5.7, 35.35)-(5.7, 32.65); L6 (5.9, 32.45)-(10.2, 32.45); L7 (10.2, 32.45)-(10.2, 33.1); L8 (10.2, 33.1)-(10.479, 33.379); L9 (10.621, 33.379)-(11.55, 32.45); L10 (11.55, 32.45)-(14.3, 32.45); L11 (15.2, 33.35)-(15.2, 34.65); L12 (14.3, 35.55)-(11.55, 35.55); L13 (11.55, 35.55)-(10.621, 34.621); L14 (10.479, 34.621)-(10.2, 34.9); L15 (10.2, 34.9)-(10.2, 35.55); L16 (10.2, 35.55)-(5.9, 35.55); L17 (5.7, 31.85)-(5.7, 29.15); L18 (5.9, 28.95)-(10.2, 28.95); L19 (10.2, 28.95)-(10.2, 29.6); L20 (10.2, 29.6)-(10.479, 29.879); L21 (10.621, 29.879)-(11.55, 28.95); L22 (11.55, 28.95)-(14.3, 28.95); L23 (15.2, 29.85)-(15.2, 31.15); L24 (14.3, 32.05)-(11.55, 32.05); L25 (11.55, 32.05)-(10.621, 31.121); L26 (10.479, 31.121)-(10.2, 31.4); L27 (10.2, 31.4)-(10.2, 32.05); L28 (10.2, 32.05)-(5.9, 32.05); L29 (5.7, 28.35)-(5.7, 25.65); L30 (5.9, 25.45)-(10.2, 25.45); L31 (10.2, 25.45)-(10.2, 26.1); L32 (10.2, 26.1)-(10.479, 26.379); L33 (10.621, 26.379)-(11.55, 25.45); L34 (11.55, 25.45)-(14.3, 25.45); L35 (15.2, 26.35)-(15.2, 27.65); L36 (14.3, 28.55)-(11.55, 28.55); L37 (11.55, 28.55)-(10.621, 27.621); L38 (10.479, 27.621)-(10.2, 27.9); L39 (10.2, 27.9)-(10.2, 28.55); L40 (10.2, 28.55)-(5.9, 28.55); L41 (5.7, 24.85)-(5.7, 22.15); L42 (5.9, 21.95)-(10.2, 21.95); L43 (10.2, 21.95)-(10.2, 22.6); L44 (10.2, 22.6)-(10.479, 22.879); L45 (10.621, 22.879)-(11.55, 21.95); L46 (11.55, 21.95)-(14.3, 21.95); L47 (15.2, 22.85)-(15.2, 24.15); L48 (14.3, 25.05)-(11.55, 25.05); L49 (11.55, 25.05)-(10.621, 24.121); L50 (10.479, 24.121)-(10.2, 24.4); L51 (10.2, 24.4)-(10.2, 25.05); L52 (10.2, 25.05)-(5.9, 25.05); L53 (5.7, 21.35)-(5.7, 18.65); L54 (5.9, 18.45)-(10.2, 18.45); L55 (10.2, 18.45)-(10.2, 19.1); L56 (10.2, 19.1)-(10.479, 19.379); L57 (10.621, 19.379)-(11.55, 18.45); L58 (11.55, 18.45)-(14.3, 18.45); L59 (15.2, 19.35)-(15.2, 20.65); L60 (14.3, 21.55)-(11.55, 21.55); L61 (11.55, 21.55)-(10.621, 20.621); L62 (10.479, 20.621)-(10.2, 20.9); L63 (10.2, 20.9)-(10.2, 21.55); L64 (10.2, 21.55)-(5.9, 21.55); A1 r 0.2 centre (5.9, 32.65) between (5.7, 32.65) and (5.9, 32.45); A2 r 0.1 centre (10.55, 33.309) between (10.621, 33.379) and (10.479, 33.379); A3 r 0.9 centre (14.3, 33.35) between (14.3, 32.45) and (15.2, 33.35); A4 r 0.9 centre (14.3, 34.65) between (15.2, 34.65) and (14.3, 35.55); A5 r 0.1 centre (10.55, 34.691) between (10.479, 34.621) and (10.621, 34.621); A6 r 0.2 centre (5.9, 35.35) between (5.9, 35.55) and (5.7, 35.35); A7 r 0.2 centre (5.9, 29.15) between (5.7, 29.15) and (5.9, 28.95); A8 r 0.1 centre (10.55, 29.809) between (10.621, 29.879) and (10.479, 29.879); A9 r 0.9 centre (14.3, 29.85) between (14.3, 28.95) and (15.2, 29.85); A10 r 0.9 centre (14.3, 31.15) between (15.2, 31.15) and (14.3, 32.05); A11 r 0.1 centre (10.55, 31.191) between (10.479, 31.121) and (10.621, 31.121); A12 r 0.2 centre (5.9, 31.85) between (5.9, 32.05) and (5.7, 31.85); A13 r 0.2 centre (5.9, 25.65) between (5.7, 25.65) and (5.9, 25.45); A14 r 0.1 centre (10.55, 26.309) between (10.621, 26.379) and (10.479, 26.379); A15 r 0.9 centre (14.3, 26.35) between (14.3, 25.45) and (15.2, 26.35); A16 r 0.9 centre (14.3, 27.65) between (15.2, 27.65) and (14.3, 28.55); A17 r 0.1 centre (10.55, 27.691) between (10.479, 27.621) and (10.621, 27.621); A18 r 0.2 centre (5.9, 28.35) between (5.9, 28.55) and (5.7, 28.35); A19 r 0.2 centre (5.9, 22.15) between (5.7, 22.15) and (5.9, 21.95); A20 r 0.1 centre (10.55, 22.809) between (10.621, 22.879) and (10.479, 22.879); A21 r 0.9 centre (14.3, 22.85) between (14.3, 21.95) and (15.2, 22.85); A22 r 0.9 centre (14.3, 24.15) between (15.2, 24.15) and (14.3, 25.05); A23 r 0.1 centre (10.55, 24.191) between (10.479, 24.121) and (10.621, 24.121); A24 r 0.2 centre (5.9, 24.85) between (5.9, 25.05) and (5.7, 24.85); A25 r 0.2 centre (5.9, 18.65) between (5.7, 18.65) and (5.9, 18.45); A26 r 0.1 centre (10.55, 19.309) between (10.621, 19.379) and (10.479, 19.379); A27 r 0.9 centre (14.3, 19.35) between (14.3, 18.45) and (15.2, 19.35); A28 r 0.9 centre (14.3, 20.65) between (15.2, 20.65) and (14.3, 21.55); A29 r 0.1 centre (10.55, 20.691) between (10.479, 20.621) and (10.621, 20.621); A30 r 0.2 centre (5.9, 21.35) between (5.9, 21.55) and (5.7, 21.35)
  constraints: 128 end point, 60 point on circle, 30 centre point
extrude "Extrusion43" join sketch "Sketch_39" distance "d128" = 8; taper "d129" = 0 deg
sketch "Sketch_40"
  geometry: L1 (5.2, 1.35)-(16, 1.35); L2 (16, 1.35)-(16, 12.65); L3 (16, 12.65)-(5.2, 12.65); L4 (5.2, 12.65)-(5.2, 1.35); L5 (5.7, 11.85)-(5.7, 9.15); L6 (5.9, 8.95)-(10.2, 8.95); L7 (10.2, 8.95)-(10.2, 9.6); L8 (10.2, 9.6)-(10.479, 9.879); L9 (10.621, 9.879)-(11.55, 8.95); L10 (11.55, 8.95)-(14.3, 8.95); L11 (15.2, 9.85)-(15.2, 11.15); L12 (14.3, 12.05)-(11.55, 12.05); L13 (11.55, 12.05)-(10.621, 11.121); L14 (10.479, 11.121)-(10.2, 11.4); L15 (10.2, 11.4)-(10.2, 12.05); L16 (10.2, 12.05)-(5.9, 12.05); L17 (5.7, 8.35)-(5.7, 5.65); L18 (5.9, 5.45)-(10.2, 5.45); L19 (10.2, 5.45)-(10.2, 6.1); L20 (10.2, 6.1)-(10.479, 6.379); L21 (10.621, 6.379)-(11.55, 5.45); L22 (11.55, 5.45)-(14.3, 5.45); L23 (15.2, 6.35)-(15.2, 7.65); L24 (14.3, 8.55)-(11.55, 8.55); L25 (11.55, 8.55)-(10.621, 7.621); L26 (10.479, 7.621)-(10.2, 7.9); L27 (10.2, 7.9)-(10.2, 8.55); L28 (10.2, 8.55)-(5.9, 8.55); L29 (5.7, 4.85)-(5.7, 2.15); L30 (5.9, 1.95)-(10.2, 1.95); L31 (10.2, 1.95)-(10.2, 2.6); L32 (10.2, 2.6)-(10.479, 2.879); L33 (10.621, 2.879)-(11.55, 1.95); L34 (11.55, 1.95)-(14.3, 1.95); L35 (15.2, 2.85)-(15.2, 4.15); L36 (14.3, 5.05)-(11.55, 5.05); L37 (11.55, 5.05)-(10.621, 4.121); L38 (10.479, 4.121)-(10.2, 4.4); L39 (10.2, 4.4)-(10.2, 5.05); L40 (10.2, 5.05)-(5.9, 5.05); A1 r 0.2 centre (5.9, 9.15) between (5.7, 9.15) and (5.9, 8.95); A2 r 0.1 centre (10.55, 9.809) between (10.621, 9.879) and (10.479, 9.879); A3 r 0.9 centre (14.3, 9.85) between (14.3, 8.95) and (15.2, 9.85); A4 r 0.9 centre (14.3, 11.15) between (15.2, 11.15) and (14.3, 12.05); A5 r 0.1 centre (10.55, 11.191) between (10.479, 11.121) and (10.621, 11.121); A6 r 0.2 centre (5.9, 11.85) between (5.9, 12.05) and (5.7, 11.85); A7 r 0.2 centre (5.9, 5.65) between (5.7, 5.65) and (5.9, 5.45); A8 r 0.1 centre (10.55, 6.309) between (10.621, 6.379) and (10.479, 6.379); A9 r 0.9 centre (14.3, 6.35) between (14.3, 5.45) and (15.2, 6.35); A10 r 0.9 centre (14.3, 7.65) between (15.2, 7.65) and (14.3, 8.55); A11 r 0.1 centre (10.55, 7.691) between (10.479, 7.621) and (10.621, 7.621); A12 r 0.2 centre (5.9, 8.35) between (5.9, 8.55) and (5.7, 8.35); A13 r 0.2 centre (5.9, 2.15) between (5.7, 2.15) and (5.9, 1.95); A14 r 0.1 centre (10.55, 2.809) between (10.621, 2.879) and (10.479, 2.879); A15 r 0.9 centre (14.3, 2.85) between (14.3, 1.95) and (15.2, 2.85); A16 r 0.9 centre (14.3, 4.15) between (15.2, 4.15) and (14.3, 5.05); A17 r 0.1 centre (10.55, 4.191) between (10.479, 4.121) and (10.621, 4.121); A18 r 0.2 centre (5.9, 4.85) between (5.9, 5.05) and (5.7, 4.85)
  constraints: 80 end point, 36 point on circle, 18 centre point
extrude "Extrusion44" join sketch "Sketch_40" distance "d130" = 8; taper "d131" = 0 deg
sketch "Sketch_41"
  geometry: L1 (9.2, -17.365)-(9.88, -16.972); L2 (9.88, -16.972)-(9.88, -20.268); L3 (9.88, -20.268)-(9.2, -19.875); L4 (9.2, -19.875)-(9.2, -21.16); L5 (9.2, -21.16)-(14.115, -21.16); L6 (14.115, -21.16)-(14.115, -20.741); L7 (14.115, -16.499)-(14.115, -15.661); L8 (14.115, -11.419)-(14.115, -10.581); L9 (14.115, -6.339)-(14.115, -5.501); L10 (14.115, -1.259)-(14.115, -0.84); L11 (14.115, -0.84)-(9.2, -0.84); L12 (9.2, -0.84)-(9.2, -2.125); L13 (9.2, -2.125)-(9.88, -1.732); L14 (9.88, -1.732)-(9.88, -5.028); L15 (9.88, -5.028)-(9.2, -4.635); L16 (9.2, -4.635)-(9.2, -7.205); L17 (9.2, -7.205)-(9.88, -6.812); L18 (9.88, -6.812)-(9.88, -10.108); L19 (9.88, -10.108)-(9.2, -9.715); L20 (9.2, -9.715)-(9.2, -12.285); L21 (9.2, -12.285)-(9.88, -11.892); L22 (9.88, -11.892)-(9.88, -15.188); L23 (9.88, -15.188)-(9.2, -14.795); L24 (9.2, -14.795)-(9.2, -17.365); A1 r 2.915 centre (12.115, -18.62) between (14.115, -20.741) and (14.115, -16.499); A2 r 2.915 centre (12.115, -13.54) between (14.115, -15.661) and (14.115, -11.419); A3 r 2.915 centre (12.115, -8.46) between (14.115, -10.581) and (14.115, -6.339); A4 r 2.915 centre (12.115, -3.38) between (14.115, -5.501) and (14.115, -1.259)
  constraints: 48 end point, 8 point on circle, 4 centre point
extrude "Extrusion45" join sketch "Sketch_41" distance "d132" = 8; taper "d133" = 0 deg
sketch "Sketch_44"
  geometry: L1 (7.35, 34.298)-(7.35, 33.702); L2 (7.452, 33.6)-(8.048, 33.6); L3 (8.15, 33.702)-(8.15, 34.298); L4 (8.048, 34.4)-(7.452, 34.4); A1 r 0.102 centre (7.452, 33.702) between (7.35, 33.702) and (7.452, 33.6); A2 r 0.102 centre (8.048, 33.702) between (8.048, 33.6) and (8.15, 33.702); A3 r 0.102 centre (8.048, 34.298) between (8.15, 34.298) and (8.048, 34.4); A4 r 0.102 centre (7.452, 34.298) between (7.452, 34.4) and (7.35, 34.298)
  constraints: 8 end point, 8 point on circle, 4 centre point
extrude "Extrusion46" join sketch "Sketch_44" distance "d134" = 5.25; taper "d135" = 0 deg
sketch "Pattern_10_SKETCH_1"
  geometry: L1 (7.35, 30.798)-(7.35, 30.202); L2 (7.452, 30.1)-(8.048, 30.1); L3 (8.15, 30.202)-(8.15, 30.798); L4 (8.048, 30.9)-(7.452, 30.9); A1 r 0.102 centre (7.452, 30.202) between (7.35, 30.202) and (7.452, 30.1); A2 r 0.102 centre (8.048, 30.202) between (8.048, 30.1) and (8.15, 30.202); A3 r 0.102 centre (8.048, 30.798) between (8.15, 30.798) and (8.048, 30.9); A4 r 0.102 centre (7.452, 30.798) between (7.452, 30.9) and (7.35, 30.798)
  constraints: 8 end point, 8 point on circle, 4 centre point
sketch "Pattern_10_SKETCH_2"
  geometry: L1 (7.35, 27.298)-(7.35, 26.702); L2 (7.452, 26.6)-(8.048, 26.6); L3 (8.15, 26.702)-(8.15, 27.298); L4 (8.048, 27.4)-(7.452, 27.4); A1 r 0.102 centre (7.452, 26.702) between (7.35, 26.702) and (7.452, 26.6); A2 r 0.102 centre (8.048, 26.702) between (8.048, 26.6) and (8.15, 26.702); A3 r 0.102 centre (8.048, 27.298) between (8.15, 27.298) and (8.048, 27.4); A4 r 0.102 centre (7.452, 27.298) between (7.452, 27.4) and (7.35, 27.298)
  constraints: 8 end point, 8 point on circle, 4 centre point
sketch "Pattern_10_SKETCH_3"
  geometry: L1 (7.35, 23.798)-(7.35, 23.202); L2 (7.452, 23.1)-(8.048, 23.1); L3 (8.15, 23.202)-(8.15, 23.798); L4 (8.048, 23.9)-(7.452, 23.9); A1 r 0.102 centre (7.452, 23.202) between (7.35, 23.202) and (7.452, 23.1); A2 r 0.102 centre (8.048, 23.202) between (8.048, 23.1) and (8.15, 23.202); A3 r 0.102 centre (8.048, 23.798) between (8.15, 23.798) and (8.048, 23.9); A4 r 0.102 centre (7.452, 23.798) between (7.452, 23.9) and (7.35, 23.798)
  constraints: 8 end point, 8 point on circle, 4 centre point
sketch "Pattern_10_SKETCH_4"
  geometry: L1 (7.35, 20.298)-(7.35, 19.702); L2 (7.452, 19.6)-(8.048, 19.6); L3 (8.15, 19.702)-(8.15, 20.298); L4 (8.048, 20.4)-(7.452, 20.4); A1 r 0.102 centre (7.452, 19.702) between (7.35, 19.702) and (7.452, 19.6); A2 r 0.102 centre (8.048, 19.702) between (8.048, 19.6) and (8.15, 19.702); A3 r 0.102 centre (8.048, 20.298) between (8.15, 20.298) and (8.048, 20.4); A4 r 0.102 centre (7.452, 20.298) between (7.452, 20.4) and (7.35, 20.298)
  constraints: 8 end point, 8 point on circle, 4 centre point
sketch "Pattern_10_SKETCH_5"
  geometry: L1 (12.85, 34.298)-(12.85, 33.702); L2 (12.952, 33.6)-(13.548, 33.6); L3 (13.65, 33.702)-(13.65, 34.298); L4 (13.548, 34.4)-(12.952, 34.4); A1 r 0.102 centre (12.952, 33.702) between (12.85, 33.702) and (12.952, 33.6); A2 r 0.102 centre (13.548, 33.702) between (13.548, 33.6) and (13.65, 33.702); A3 r 0.102 centre (13.548, 34.298) between (13.65, 34.298) and (13.548, 34.4); A4 r 0.102 centre (12.952, 34.298) between (12.952, 34.4) and (12.85, 34.298)
  constraints: 8 end point, 8 point on circle, 4 centre point
sketch "Pattern_10_SKETCH_6"
  geometry: L1 (12.85, 30.798)-(12.85, 30.202); L2 (12.952, 30.1)-(13.548, 30.1); L3 (13.65, 30.202)-(13.65, 30.798); L4 (13.548, 30.9)-(12.952, 30.9); A1 r 0.102 centre (12.952, 30.202) between (12.85, 30.202) and (12.952, 30.1); A2 r 0.102 centre (13.548, 30.202) between (13.548, 30.1) and (13.65, 30.202); A3 r 0.102 centre (13.548, 30.798) between (13.65, 30.798) and (13.548, 30.9); A4 r 0.102 centre (12.952, 30.798) between (12.952, 30.9) and (12.85, 30.798)
  constraints: 8 end point, 8 point on circle, 4 centre point
sketch "Pattern_10_SKETCH_7"
  geometry: L1 (12.85, 27.298)-(12.85, 26.702); L2 (12.952, 26.6)-(13.548, 26.6); L3 (13.65, 26.702)-(13.65, 27.298); L4 (13.548, 27.4)-(12.952, 27.4); A1 r 0.102 centre (12.952, 26.702) between (12.85, 26.702) and (12.952, 26.6); A2 r 0.102 centre (13.548, 26.702) between (13.548, 26.6) and (13.65, 26.702); A3 r 0.102 centre (13.548, 27.298) between (13.65, 27.298) and (13.548, 27.4); A4 r 0.102 centre (12.952, 27.298) between (12.952, 27.4) and (12.85, 27.298)
  constraints: 8 end point, 8 point on circle, 4 centre point
sketch "Pattern_10_SKETCH_8"
  geometry: L1 (12.85, 23.798)-(12.85, 23.202); L2 (12.952, 23.1)-(13.548, 23.1); L3 (13.65, 23.202)-(13.65, 23.798); L4 (13.548, 23.9)-(12.952, 23.9); A1 r 0.102 centre (12.952, 23.202) between (12.85, 23.202) and (12.952, 23.1); A2 r 0.102 centre (13.548, 23.202) between (13.548, 23.1) and (13.65, 23.202); A3 r 0.102 centre (13.548, 23.798) between (13.65, 23.798) and (13.548, 23.9); A4 r 0.102 centre (12.952, 23.798) between (12.952, 23.9) and (12.85, 23.798)
  constraints: 8 end point, 8 point on circle, 4 centre point
sketch "Pattern_10_SKETCH_9"
  geometry: L1 (12.85, 20.298)-(12.85, 19.702); L2 (12.952, 19.6)-(13.548, 19.6); L3 (13.65, 19.702)-(13.65, 20.298); L4 (13.548, 20.4)-(12.952, 20.4); A1 r 0.102 centre (12.952, 19.702) between (12.85, 19.702) and (12.952, 19.6); A2 r 0.102 centre (13.548, 19.702) between (13.548, 19.6) and (13.65, 19.702); A3 r 0.102 centre (13.548, 20.298) between (13.65, 20.298) and (13.548, 20.4); A4 r 0.102 centre (12.952, 20.298) between (12.952, 20.4) and (12.85, 20.298)
  constraints: 8 end point, 8 point on circle, 4 centre point
sketch "Pattern_10_SKETCH_10"
  geometry: L1 (7.35, 10.798)-(7.35, 10.202); L2 (7.452, 10.1)-(8.048, 10.1); L3 (8.15, 10.202)-(8.15, 10.798); L4 (8.048, 10.9)-(7.452, 10.9); A1 r 0.102 centre (7.452, 10.202) between (7.35, 10.202) and (7.452, 10.1); A2 r 0.102 centre (8.048, 10.202) between (8.048, 10.1) and (8.15, 10.202); A3 r 0.102 centre (8.048, 10.798) between (8.15, 10.798) and (8.048, 10.9); A4 r 0.102 centre (7.452, 10.798) between (7.452, 10.9) and (7.35, 10.798)
  constraints: 8 end point, 8 point on circle, 4 centre point
sketch "Pattern_10_SKETCH_11"
  geometry: L1 (7.35, 7.298)-(7.35, 6.702); L2 (7.452, 6.6)-(8.048, 6.6); L3 (8.15, 6.702)-(8.15, 7.298); L4 (8.048, 7.4)-(7.452, 7.4); A1 r 0.102 centre (7.452, 6.702) between (7.35, 6.702) and (7.452, 6.6); A2 r 0.102 centre (8.048, 6.702) between (8.048, 6.6) and (8.15, 6.702); A3 r 0.102 centre (8.048, 7.298) between (8.15, 7.298) and (8.048, 7.4); A4 r 0.102 centre (7.452, 7.298) between (7.452, 7.4) and (7.35, 7.298)
  constraints: 8 end point, 8 point on circle, 4 centre point
sketch "Pattern_10_SKETCH_12"
  geometry: L1 (7.35, 3.798)-(7.35, 3.202); L2 (7.452, 3.1)-(8.048, 3.1); L3 (8.15, 3.202)-(8.15, 3.798); L4 (8.048, 3.9)-(7.452, 3.9); A1 r 0.102 centre (7.452, 3.202) between (7.35, 3.202) and (7.452, 3.1); A2 r 0.102 centre (8.048, 3.202) between (8.048, 3.1) and (8.15, 3.202); A3 r 0.102 centre (8.048, 3.798) between (8.15, 3.798) and (8.048, 3.9); A4 r 0.102 centre (7.452, 3.798) between (7.452, 3.9) and (7.35, 3.798)
  constraints: 8 end point, 8 point on circle, 4 centre point
sketch "Pattern_10_SKETCH_13"
  geometry: L1 (12.85, 10.798)-(12.85, 10.202); L2 (12.952, 10.1)-(13.548, 10.1); L3 (13.65, 10.202)-(13.65, 10.798); L4 (13.548, 10.9)-(12.952, 10.9); A1 r 0.102 centre (12.952, 10.202) between (12.85, 10.202) and (12.952, 10.1); A2 r 0.102 centre (13.548, 10.202) between (13.548, 10.1) and (13.65, 10.202); A3 r 0.102 centre (13.548, 10.798) between (13.65, 10.798) and (13.548, 10.9); A4 r 0.102 centre (12.952, 10.798) between (12.952, 10.9) and (12.85, 10.798)
  constraints: 8 end point, 8 point on circle, 4 centre point
sketch "Pattern_10_SKETCH_14"
  geometry: L1 (12.85, 7.298)-(12.85, 6.702); L2 (12.952, 6.6)-(13.548, 6.6); L3 (13.65, 6.702)-(13.65, 7.298); L4 (13.548, 7.4)-(12.952, 7.4); A1 r 0.102 centre (12.952, 6.702) between (12.85, 6.702) and (12.952, 6.6); A2 r 0.102 centre (13.548, 6.702) between (13.548, 6.6) and (13.65, 6.702); A3 r 0.102 centre (13.548, 7.298) between (13.65, 7.298) and (13.548, 7.4); A4 r 0.102 centre (12.952, 7.298) between (12.952, 7.4) and (12.85, 7.298)
  constraints: 8 end point, 8 point on circle, 4 centre point
sketch "Pattern_10_SKETCH_15"
  geometry: L1 (12.85, 3.798)-(12.85, 3.202); L2 (12.952, 3.1)-(13.548, 3.1); L3 (13.65, 3.202)-(13.65, 3.798); L4 (13.548, 3.9)-(12.952, 3.9); A1 r 0.102 centre (12.952, 3.202) between (12.85, 3.202) and (12.952, 3.1); A2 r 0.102 centre (13.548, 3.202) between (13.548, 3.1) and (13.65, 3.202); A3 r 0.102 centre (13.548, 3.798) between (13.65, 3.798) and (13.548, 3.9); A4 r 0.102 centre (12.952, 3.798) between (12.952, 3.9) and (12.85, 3.798)
  constraints: 8 end point, 8 point on circle, 4 centre point
extrude "Extrusion47" join sketch "Pattern_10_SKETCH_1" distance "d136" = 5.25; taper "d137" = 0 deg
extrude "Extrusion48" join sketch "Pattern_10_SKETCH_2" distance "d138" = 5.25; taper "d139" = 0 deg
extrude "Extrusion49" join sketch "Pattern_10_SKETCH_3" distance "d140" = 5.25; taper "d141" = 0 deg
extrude "Extrusion50" join sketch "Pattern_10_SKETCH_4" distance "d142" = 5.25; taper "d143" = 0 deg
extrude "Extrusion51" join sketch "Pattern_10_SKETCH_5" distance "d144" = 5.25; taper "d145" = 0 deg
extrude "Extrusion52" join sketch "Pattern_10_SKETCH_6" distance "d146" = 5.25; taper "d147" = 0 deg
extrude "Extrusion53" join sketch "Pattern_10_SKETCH_7" distance "d148" = 5.25; taper "d149" = 0 deg
extrude "Extrusion54" join sketch "Pattern_10_SKETCH_8" distance "d150" = 5.25; taper "d151" = 0 deg
extrude "Extrusion55" join sketch "Pattern_10_SKETCH_9" distance "d152" = 5.25; taper "d153" = 0 deg
extrude "Extrusion56" join sketch "Pattern_10_SKETCH_10" distance "d154" = 5.25; taper "d155" = 0 deg
extrude "Extrusion57" join sketch "Pattern_10_SKETCH_11" distance "d156" = 5.25; taper "d157" = 0 deg
extrude "Extrusion58" join sketch "Pattern_10_SKETCH_12" distance "d158" = 5.25; taper "d159" = 0 deg
extrude "Extrusion59" join sketch "Pattern_10_SKETCH_13" distance "d160" = 5.25; taper "d161" = 0 deg
extrude "Extrusion60" join sketch "Pattern_10_SKETCH_14" distance "d162" = 5.25; taper "d163" = 0 deg
extrude "Extrusion61" join sketch "Pattern_10_SKETCH_15" distance "d164" = 5.25; taper "d165" = 0 deg
sketch "Sketch64"
  geometry: 1 further point
hole "Hole1" sketch "Sketch64" at (12.115, -3.38) diameter "d166" = 1.4; stored, may be unused: countersink angle "d170" = 90 deg, drill point angle "d172" = 0 deg; dims "d167" = 6, "d168" = 2.8, "d169" = 1, "d171" = 7
pattern_linear "Rectangular Pattern8" dims "d175" = 5.08, "d178" = 0
sketch "Sketch_46"
  geometry: L1 (170.3, 40.8)-(169.9, 40.8); L2 (169.9, 40.8)-(169.9, 42.3); L3 (169.9, 42.3)-(170.2, 42.3); L4 (170.3, 42.4)-(170.3, 40.8); L5 (170.3, 40.8)-(169.9, 40.8); A1 r 0.1 centre (170.2, 42.4) between (170.2, 42.3) and (170.3, 42.4)
  constraints: 10 end point, 2 point on circle, 1 centre point
revolve "Revolution3" sketch "Sketch_46" stored, may be unused: angle "d179" = 360 deg
sketch "Pattern_11_SKETCH_1"
  geometry: L1 (170.3, 29.8)-(169.9, 29.8); L2 (169.9, 29.8)-(169.9, 31.3); L3 (169.9, 31.3)-(170.2, 31.3); L4 (170.3, 31.4)-(170.3, 29.8); L5 (170.3, 29.8)-(169.9, 29.8); A1 r 0.1 centre (170.2, 31.4) between (170.2, 31.3) and (170.3, 31.4)
  constraints: 10 end point, 2 point on circle, 1 centre point
sketch "Pattern_11_SKETCH_2"
  geometry: L1 (170.3, 23.3)-(169.9, 23.3); L2 (169.9, 23.3)-(169.9, 24.8); L3 (169.9, 24.8)-(170.2, 24.8); L4 (170.3, 24.9)-(170.3, 23.3); L5 (170.3, 23.3)-(169.9, 23.3); A1 r 0.1 centre (170.2, 24.9) between (170.2, 24.8) and (170.3, 24.9)
  constraints: 10 end point, 2 point on circle, 1 centre point
sketch "Pattern_11_SKETCH_3"
  geometry: L1 (170.3, 16.8)-(169.9, 16.8); L2 (169.9, 16.8)-(169.9, 18.3); L3 (169.9, 18.3)-(170.2, 18.3); L4 (170.3, 18.4)-(170.3, 16.8); L5 (170.3, 16.8)-(169.9, 16.8); A1 r 0.1 centre (170.2, 18.4) between (170.2, 18.3) and (170.3, 18.4)
  constraints: 10 end point, 2 point on circle, 1 centre point
sketch "Pattern_11_SKETCH_4"
  geometry: L1 (170.3, 10.3)-(169.9, 10.3); L2 (169.9, 10.3)-(169.9, 11.8); L3 (169.9, 11.8)-(170.2, 11.8); L4 (170.3, 11.9)-(170.3, 10.3); L5 (170.3, 10.3)-(169.9, 10.3); A1 r 0.1 centre (170.2, 11.9) between (170.2, 11.8) and (170.3, 11.9)
  constraints: 10 end point, 2 point on circle, 1 centre point
sketch "Pattern_11_SKETCH_5"
  geometry: L1 (170.3, 40.8)-(169.9, 40.8); L2 (169.9, 40.8)-(169.9, 42.3); L3 (169.9, 42.3)-(170.2, 42.3); L4 (170.3, 42.4)-(170.3, 40.8); L5 (170.3, 40.8)-(169.9, 40.8); A1 r 0.1 centre (170.2, 42.4) between (170.2, 42.3) and (170.3, 42.4)
  constraints: 10 end point, 2 point on circle, 1 centre point
revolve "Revolution4" stored, may be unused: angle "d180" = 360 deg
revolve "Revolution5" stored, may be unused: angle "d181" = 360 deg
revolve "Revolution6" stored, may be unused: angle "d182" = 360 deg
revolve "Revolution7" stored, may be unused: angle "d183" = 360 deg
revolve "Revolution8" stored, may be unused: angle "d184" = 360 deg
sketch "Sketch_48"
  geometry: L1 (167.9, -17)-(156.064, -17); L2 (156.064, -17)-(157, -15.379); L3 (157, -15.379)-(167.9, -15.379); L4 (167.9, -15.379)-(167.9, -17); L5 (167.9, -17)-(156.064, -17)
  constraints: 10 end point
revolve "Revolution9" sketch "Sketch_48" stored, may be unused: angle "d185" = 360 deg
thread "Thread1" dims "d186" = 10.9, "d187" = 0
sketch "Sketch_49"
  geometry: L1 (167.9, 17)-(156.064, 17); L2 (156.064, 17)-(157, 18.621); L3 (157, 18.621)-(167.9, 18.621); L4 (167.9, 18.621)-(167.9, 17); L5 (167.9, 17)-(156.064, 17)
  constraints: 10 end point
revolve "Revolution10" sketch "Sketch_49" stored, may be unused: angle "d188" = 360 deg
thread "Thread2" dims "d189" = 10.9, "d190" = 0
sketch "Sketch_50"
  geometry: L1 (184.2, -1.3)-(190, -1.3); L2 (190, -1.3)-(190, 13.7); L3 (190, 13.7)-(184.2, 13.7); A1 r 8 centre (186.984, 6.2) between (184.2, 13.7) and (184.2, -1.3)
  constraints: 6 end point, 2 point on circle, 1 centre point
extrude "Extrusion62" cut sketch "Sketch_50" stored distance "d191" = 60; taper "d192" = 0 deg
